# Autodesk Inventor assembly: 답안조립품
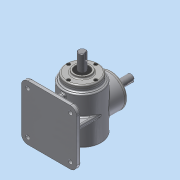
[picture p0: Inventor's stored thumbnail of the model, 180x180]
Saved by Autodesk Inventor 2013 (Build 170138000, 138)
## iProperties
Created: 2015-07
Part Number: 답안조립품
Document SubType Name: Assembly
Designer: dgall
Author: dgall
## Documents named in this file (14)
- C:\Users\dgall\Desktop\450705V1014\답안조립품.iam
- C:\Users\dgall\Desktop\450705V1014\1번본체.ipt
- C:\Users\dgall\Desktop\450705V1014\커버.ipt
- C:\Users\dgall\Desktop\450705V1014\메인 축.ipt
- 메인 축.ipt
- C:\Users\dgall\Desktop\450705V1014\서브 축.ipt
- 서브 축.ipt
- C:\Users\dgall\Desktop\450705V1014\메인 베벨기어.ipt
- C:\Users\dgall\Desktop\450705V1014\베어링 6203.ipt
- C:\Users\dgall\Desktop\450705V1014\오일실.ipt
- C:\Users\dgall\Desktop\450705V1014\키 5x5.ipt
- C:\Users\dgall\Desktop\450705V1014\키 4x4.ipt
- C:\Users\dgall\Desktop\450705V1014\M4.ipt
- C:\Users\dgall\Desktop\450705V1014\서브 베벨기어.ipt
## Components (9 placed, 2 different names)
1. 1번본체:1
2. M4:1
3. M4:2
4. M4:3
5. M4:4
6. M4:5
7. M4:6
8. M4:7
9. M4:8
